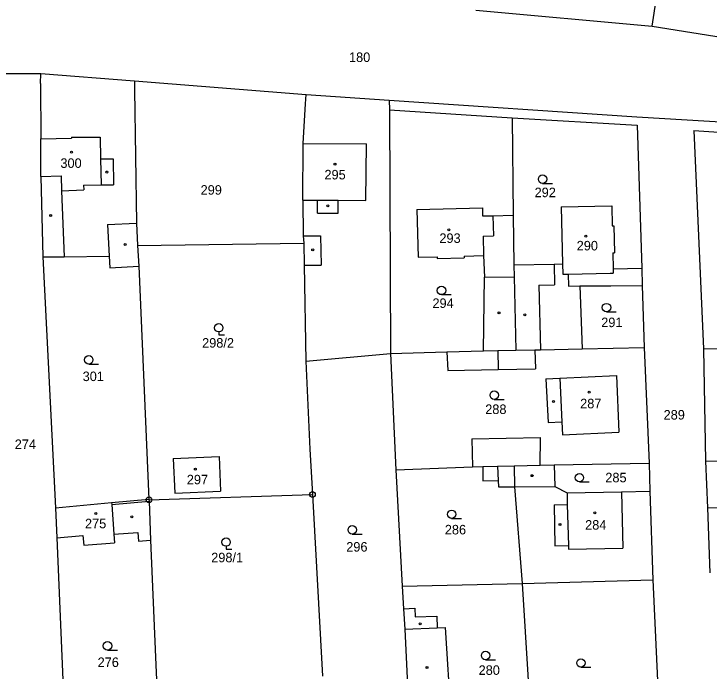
# Model space of a CAD drawing. Extents: x -779596 to -776743, y -1030330 to -1024513.
# Drawn here: x -778309.6 to -778185.6, y -1024804.1 to -1024686.7 of the extents above; entities that cross this region are included whole.
import ezdxf

# ---------------------------------------------------------------- set-up
doc = ezdxf.new("R2010")
doc.units = 0
for name, color, linetype in [('hranice parcel', 7, 'Continuous'), ('hranice vnitřní', 7, 'Continuous'), ('kultura', 7, 'Continuous'), ('Kód', 7, 'Continuous'), ('č_ parcel šipka', 7, 'Continuous'), ('č_pacel stav_', 7, 'Continuous'), ('č_parcel poz_', 7, 'Continuous')]:
    doc.layers.add(name, color=color, linetype=linetype)

msp = doc.modelspace()

# ---------------------------------------------------------------- linework, layer by layer
at = {"layer": 'hranice parcel'}
for points in [[(-778195.72, -1024688.95), (-778193.66, -1024675.24)], [(-778227.18, -1024686.07), (-778195.72, -1024688.95)], [(-778195.72, -1024688.95), (-778150.63, -1024696.12)], [(-778314.4, -1024697.39), (-778304.84, -1024697.38)], [(-778304.89, -1024699.14), (-778304.84, -1024697.38)], [(-778304.84, -1024697.38), (-778288.11, -1024698.71)], [(-778288.11, -1024698.71), (-778288.09, -1024700.32)], [(-778288.11, -1024698.71), (-778257.48, -1024701.14)], [(-778304.89, -1024699.14), (-778304.8, -1024709.04)], [(-778288.09, -1024700.32), (-778287.75, -1024724.09)], [(-778257.56, -1024702.77), (-778257.48, -1024701.14)], [(-778257.48, -1024701.14), (-778242.63, -1024702.14)], [(-778242.63, -1024702.14), (-778198.44, -1024705.1)], [(-778242.63, -1024702.14), (-778242.62, -1024703.86)], [(-778257.98, -1024709.85), (-778257.56, -1024702.77)], [(-778242.62, -1024703.86), (-778242.43, -1024747.35)], [(-778242.62, -1024703.86), (-778220.71, -1024705.3)], [(-778220.71, -1024705.3), (-778198.39, -1024706.6)], [(-778220.71, -1024705.3), (-778220.5, -1024722.69)], [(-778198.44, -1024705.1), (-778160.55, -1024707.39)], [(-778198.39, -1024706.6), (-778197.59, -1024732.16)], [(-778188.31, -1024707.53), (-778160.55, -1024709.39)], [(-778188.31, -1024707.53), (-778186.58, -1024746.54)], [(-778304.84, -1024715.78), (-778304.8, -1024709.04)], [(-778258.06, -1024719.99), (-778257.98, -1024709.85)], [(-778304.84, -1024715.78), (-778304.46, -1024730.09)], [(-778258.06, -1024719.99), (-778257.97, -1024726.37)], [(-778211.94, -1024721.17), (-778202.94, -1024720.98)], [(-778202.94, -1024720.98), (-778202.86, -1024724.6)], [(-778237.7, -1024721.67), (-778226.01, -1024721.39)], [(-778237.7, -1024721.67), (-778237.5, -1024730.18)], [(-778226.01, -1024721.39), (-778225.98, -1024722.82)], [(-778211.94, -1024721.17), (-778211.72, -1024731.38)], [(-778225.98, -1024722.82), (-778224.13, -1024722.78)], [(-778224.13, -1024722.78), (-778220.5, -1024722.69)], [(-778220.5, -1024722.69), (-778220.39, -1024731.53)], [(-778287.75, -1024724.09), (-778287.54, -1024728.1)], [(-778202.86, -1024724.6), (-778202.56, -1024724.6)], [(-778202.56, -1024724.6), (-778202.46, -1024729.39)], [(-778257.97, -1024726.37), (-778257.91, -1024727.68)], [(-778287.54, -1024728.1), (-778257.91, -1024727.68)], [(-778287.54, -1024728.1), (-778287.35, -1024731.8)], [(-778257.91, -1024727.68), (-778257.83, -1024731.63)], [(-778202.76, -1024729.4), (-778202.46, -1024729.39)], [(-778202.76, -1024729.4), (-778202.7, -1024732.24)], [(-778304.46, -1024730.09), (-778300.64, -1024730.12)], [(-778304.46, -1024730.09), (-778302.17, -1024774.92)], [(-778300.64, -1024730.12), (-778292.6, -1024729.98)], [(-778292.6, -1024729.98), (-778292.49, -1024732.07)], [(-778237.5, -1024730.18), (-778234.07, -1024730.1)], [(-778234.07, -1024730.1), (-778234.06, -1024730.4)], [(-778234.06, -1024730.4), (-778229.29, -1024730.29)], [(-778229.29, -1024729.99), (-778225.81, -1024729.9)], [(-778229.29, -1024729.99), (-778229.29, -1024730.29)], [(-778225.81, -1024729.9), (-778225.66, -1024733.77)], [(-778292.49, -1024732.07), (-778287.35, -1024731.8)], [(-778287.35, -1024731.8), (-778285.52, -1024773.4)], [(-778257.83, -1024731.63), (-778257.51, -1024748.73)], [(-778220.39, -1024731.53), (-778213.2, -1024731.4)], [(-778220.39, -1024731.53), (-778220.36, -1024733.69)], [(-778213.2, -1024731.4), (-778211.72, -1024731.38)], [(-778202.7, -1024732.24), (-778197.59, -1024732.16)], [(-778197.59, -1024732.16), (-778197.5, -1024735.24)], [(-778225.81, -1024746.92), (-778225.66, -1024733.77)], [(-778220.36, -1024733.69), (-778220.07, -1024746.77)], [(-778208.62, -1024735.32), (-778203.12, -1024735.28)], [(-778208.62, -1024735.32), (-778208.2, -1024746.57)], [(-778203.12, -1024735.28), (-778197.5, -1024735.24)], [(-778197.5, -1024735.24), (-778197.15, -1024746.33)], [(-778242.43, -1024747.35), (-778232.36, -1024747.09)], [(-778232.36, -1024747.09), (-778225.81, -1024746.92)], [(-778225.81, -1024746.92), (-778223.29, -1024746.85)], [(-778223.29, -1024746.85), (-778220.07, -1024746.77)], [(-778220.07, -1024746.77), (-778216.64, -1024746.75)], [(-778216.64, -1024746.75), (-778215.67, -1024746.73)], [(-778215.67, -1024746.73), (-778208.2, -1024746.57)], [(-778208.2, -1024746.57), (-778197.15, -1024746.33)], [(-778197.15, -1024746.33), (-778196.28, -1024766.95)], [(-778186.58, -1024746.54), (-778174.27, -1024746.3)], [(-778186.58, -1024746.54), (-778186.2, -1024766.58)], [(-778257.51, -1024748.73), (-778242.43, -1024747.35)], [(-778242.43, -1024747.35), (-778241.49, -1024768.13)], [(-778257.51, -1024748.73), (-778256.78, -1024764.46)], [(-778214.69, -1024751.9), (-778212.2, -1024751.79)], [(-778214.69, -1024751.9), (-778214.28, -1024759.68)], [(-778212.2, -1024751.79), (-778202.11, -1024751.32)], [(-778202.11, -1024751.32), (-778201.65, -1024761.42)], [(-778214.28, -1024759.68), (-778211.85, -1024759.57)], [(-778211.85, -1024759.57), (-778211.74, -1024761.89)], [(-778211.74, -1024761.89), (-778201.65, -1024761.42)], [(-778256.78, -1024764.46), (-778256.34, -1024772.55)], [(-778281.2, -1024766.11), (-778273.01, -1024765.75)], [(-778273.01, -1024765.75), (-778272.73, -1024771.94)], [(-778281.2, -1024766.11), (-778280.92, -1024772.31)], [(-778213.21, -1024767.28), (-778196.28, -1024766.95)], [(-778196.28, -1024766.95), (-778196.11, -1024771.96)], [(-778186.2, -1024766.58), (-778165.58, -1024766.14)], [(-778186.2, -1024766.58), (-778185.87, -1024774.95)], [(-778241.49, -1024768.13), (-778227.8, -1024767.63)], [(-778241.49, -1024768.13), (-778240.31, -1024788.94)], [(-778227.8, -1024767.63), (-778225.93, -1024767.58)], [(-778225.93, -1024767.58), (-778223.31, -1024767.52)], [(-778223.31, -1024767.52), (-778220.36, -1024767.45)], [(-778220.36, -1024767.45), (-778215.7, -1024767.33)], [(-778220.36, -1024767.45), (-778220.27, -1024771.18)], [(-778215.7, -1024767.33), (-778213.21, -1024767.28)], [(-778213.21, -1024767.28), (-778213.1, -1024771.11)], [(-778280.92, -1024772.31), (-778272.73, -1024771.94)], [(-778220.27, -1024771.18), (-778218.94, -1024788.46)], [(-778213.1, -1024771.11), (-778210.9, -1024772.27)], [(-778201.19, -1024772.07), (-778196.11, -1024771.96)], [(-778196.11, -1024771.96), (-778195.58, -1024787.78)], [(-778285.52, -1024773.5), (-778256.34, -1024772.55)], [(-778256.34, -1024772.55), (-778254.57, -1024805)], [(-778210.9, -1024772.27), (-778201.19, -1024772.07)], [(-778302.17, -1024774.92), (-778292.18, -1024774.01)], [(-778292.18, -1024774.01), (-778285.52, -1024773.4)], [(-778285.52, -1024773.5), (-778285.52, -1024773.4)], [(-778285.52, -1024773.5), (-778285.51, -1024773.75)], [(-778285.51, -1024773.75), (-778285.22, -1024780.72)], [(-778302.17, -1024774.92), (-778301.94, -1024780.27)], [(-778185.87, -1024774.95), (-778180.98, -1024774.86)], [(-778185.87, -1024774.95), (-778185.42, -1024786.53)], [(-778291.77, -1024779.64), (-778287.48, -1024779.32)], [(-778287.48, -1024779.32), (-778287.37, -1024780.91)], [(-778301.94, -1024780.27), (-778297.33, -1024779.85)], [(-778301.94, -1024780.27), (-778299.71, -1024833.83)], [(-778297.33, -1024779.85), (-778297.15, -1024781.58)], [(-778291.77, -1024779.64), (-778291.66, -1024781.17)], [(-778297.15, -1024781.58), (-778291.66, -1024781.17)], [(-778287.37, -1024780.91), (-778285.22, -1024780.72)], [(-778285.22, -1024780.72), (-778284.34, -1024801.62)], [(-778218.94, -1024788.46), (-778195.58, -1024787.78)], [(-778195.58, -1024787.78), (-778193.9, -1024825.06)], [(-778240.31, -1024788.94), (-778218.94, -1024788.46)], [(-778240.31, -1024788.94), (-778240.07, -1024792.96)], [(-778218.94, -1024788.46), (-778216.34, -1024829.72)], [(-778240.07, -1024792.96), (-778238.08, -1024792.87)], [(-778240.07, -1024792.96), (-778239.85, -1024796.61)], [(-778238.08, -1024792.87), (-778238.01, -1024794.41)], [(-778238.01, -1024794.41), (-778234.16, -1024794.25)], [(-778234.16, -1024794.25), (-778234.07, -1024796.37)], [(-778239.85, -1024796.61), (-778239.11, -1024812.84)], [(-778234.07, -1024796.37), (-778232.64, -1024796.31)], [(-778232.64, -1024796.31), (-778231.66, -1024812.23)], [(-778284.34, -1024801.62), (-778282.93, -1024834.15)]]:
    msp.add_lwpolyline(points, dxfattribs=at)
at = {"layer": 'hranice vnitřní'}
for points in [[(-778299.33, -1024708.75), (-778299.33, -1024708.95)], [(-778299.33, -1024708.75), (-778294.22, -1024708.75)], [(-778294.22, -1024708.75), (-778294.15, -1024712.61)], [(-778304.8, -1024709.04), (-778299.33, -1024708.95)], [(-778257.98, -1024709.85), (-778246.71, -1024709.94)], [(-778246.8, -1024720.03), (-778246.71, -1024709.94)], [(-778294.15, -1024712.61), (-778291.92, -1024712.6)], [(-778294.15, -1024712.61), (-778294.06, -1024717.28)], [(-778291.92, -1024712.6), (-778291.83, -1024717.24)], [(-778304.84, -1024715.78), (-778301.18, -1024715.68)], [(-778301.18, -1024715.68), (-778301.14, -1024718.31)], [(-778297.17, -1024717.34), (-778294.06, -1024717.28)], [(-778297.17, -1024717.34), (-778297.16, -1024718.17)], [(-778294.06, -1024717.28), (-778291.83, -1024717.24)], [(-778301.14, -1024718.31), (-778297.16, -1024718.17)], [(-778301.14, -1024718.31), (-778300.64, -1024730.12)], [(-778258.06, -1024719.99), (-778255.42, -1024720.01)], [(-778255.44, -1024722.31), (-778255.42, -1024720.01)], [(-778255.42, -1024720.01), (-778251.73, -1024719.99)], [(-778251.75, -1024722.34), (-778251.73, -1024719.99)], [(-778251.73, -1024719.99), (-778246.8, -1024720.03)], [(-778255.44, -1024722.31), (-778251.75, -1024722.34)], [(-778224.13, -1024722.78), (-778224.04, -1024726.39)], [(-778292.89, -1024724.36), (-778287.75, -1024724.09)], [(-778292.89, -1024724.36), (-778292.6, -1024729.98)], [(-778257.97, -1024726.37), (-778254.88, -1024726.34)], [(-778254.88, -1024726.34), (-778254.8, -1024731.58)], [(-778225.89, -1024726.43), (-778224.04, -1024726.39)], [(-778225.89, -1024726.43), (-778225.81, -1024729.9)], [(-778257.83, -1024731.63), (-778254.8, -1024731.58)], [(-778213.2, -1024731.4), (-778213.12, -1024735.13)], [(-778211.72, -1024731.38), (-778211.68, -1024733.23)], [(-778202.7, -1024732.24), (-778202.68, -1024733.04)], [(-778211.68, -1024733.23), (-778210.69, -1024733.21)], [(-778210.69, -1024733.21), (-778203.19, -1024733.05)], [(-778210.69, -1024733.21), (-778210.64, -1024735.34)], [(-778203.19, -1024733.05), (-778202.68, -1024733.04)], [(-778225.66, -1024733.77), (-778220.36, -1024733.69)], [(-778215.93, -1024735.19), (-778213.12, -1024735.13)], [(-778215.93, -1024735.19), (-778215.67, -1024746.73)], [(-778210.64, -1024735.34), (-778208.62, -1024735.32)], [(-778232.36, -1024747.09), (-778232.18, -1024750.44)], [(-778223.29, -1024746.85), (-778223.2, -1024750.25)], [(-778216.64, -1024746.75), (-778216.56, -1024750.11)], [(-778232.18, -1024750.44), (-778223.2, -1024750.25)], [(-778223.2, -1024750.25), (-778216.56, -1024750.11)], [(-778212.2, -1024751.79), (-778211.85, -1024759.57)], [(-778227.91, -1024762.6), (-778215.62, -1024762.39)], [(-778227.91, -1024762.6), (-778227.8, -1024767.63)], [(-778215.7, -1024767.33), (-778215.62, -1024762.39)], [(-778225.93, -1024767.58), (-778225.91, -1024770.1)], [(-778223.31, -1024767.52), (-778223.18, -1024770.03)], [(-778225.91, -1024770.1), (-778223.18, -1024770.03)], [(-778223.18, -1024770.03), (-778223.17, -1024771.2)], [(-778223.17, -1024771.2), (-778220.27, -1024771.18)], [(-778220.27, -1024771.18), (-778213.1, -1024771.11)], [(-778210.9, -1024772.27), (-778210.86, -1024774.35)], [(-778201.19, -1024772.07), (-778200.98, -1024782.14)], [(-778292.18, -1024774.01), (-778292.16, -1024774.34)], [(-778292.16, -1024774.34), (-778285.51, -1024773.75)], [(-778292.16, -1024774.34), (-778291.77, -1024779.64)], [(-778213.22, -1024774.4), (-778210.86, -1024774.35)], [(-778213.22, -1024774.4), (-778213.07, -1024781.73)], [(-778210.86, -1024774.35), (-778210.68, -1024781.68)], [(-778213.07, -1024781.73), (-778210.68, -1024781.68)], [(-778210.68, -1024781.68), (-778210.67, -1024782.34)], [(-778210.67, -1024782.34), (-778200.98, -1024782.14)], [(-778239.85, -1024796.61), (-778234.07, -1024796.37)]]:
    msp.add_lwpolyline(points, dxfattribs=at)
at = {"layer": 'kultura'}
for points in [[(-778215.28, -1024717), (-778213.53, -1024717)], [(-778233.32, -1024736.87), (-778231.57, -1024736.87)], [(-778203.87, -1024739.92), (-778202.12, -1024739.92)], [(-778273.07, -1024743.53), (-778273.07, -1024744.03), (-778272.047, -1024744.03)], [(-778296.27, -1024749.26), (-778294.52, -1024749.26)], [(-778223.9, -1024755.57), (-778222.15, -1024755.57)], [(-778208.71, -1024770.3), (-778206.96, -1024770.3)], [(-778231.5, -1024776.84), (-778229.75, -1024776.84)], [(-778249.24, -1024779.61), (-778247.49, -1024779.61)], [(-778271.76, -1024781.8), (-778271.76, -1024782.3), (-778270.737, -1024782.3)], [(-778292.91, -1024800.33), (-778291.16, -1024800.33)], [(-778225.44, -1024802.05), (-778223.69, -1024802.05)], [(-778208.43, -1024803.39), (-778206.68, -1024803.39)]]:
    msp.add_lwpolyline(points, dxfattribs=at)
for centre, radius in [((-778299.35, -1024711.44), 0.175), ((-778252.32, -1024713.59), 0.175), ((-778293.03, -1024714.97), 0.175), ((-778215.28, -1024716.25), 0.75), ((-778253.59, -1024721.01), 0.175), ((-778303.06, -1024722.74), 0.175), ((-778231.99, -1024725.27), 0.175), ((-778207.58, -1024726.41), 0.175), ((-778289.77, -1024727.9), 0.175), ((-778256.3, -1024728.87), 0.175), ((-778233.32, -1024736.12), 0.75), ((-778203.87, -1024739.17), 0.75), ((-778223.05, -1024740.1), 0.175), ((-778218.42, -1024740.49), 0.175), ((-778273.07, -1024742.78), 0.75), ((-778296.27, -1024748.51), 0.75), ((-778223.9, -1024754.82), 0.75), ((-778206.96, -1024754.3), 0.175), ((-778213.33, -1024755.93), 0.175), ((-778277.24, -1024768.05), 0.175), ((-778217.16, -1024769.19), 0.175), ((-778208.71, -1024769.55), 0.75), ((-778231.5, -1024776.09), 0.75), ((-778205.94, -1024775.84), 0.175), ((-778295.02, -1024775.97), 0.175), ((-778288.55, -1024776.54), 0.175), ((-778249.24, -1024778.86), 0.75), ((-778212.17, -1024777.92), 0.175), ((-778271.76, -1024781.05), 0.75), ((-778237.12, -1024795.63), 0.175), ((-778292.91, -1024799.58), 0.75), ((-778225.44, -1024801.3), 0.75), ((-778208.43, -1024802.64), 0.75), ((-778235.9, -1024803.44), 0.175)]:
    msp.add_circle(centre, radius, dxfattribs=at)
at = {"layer": 'Kód'}
for centre, radius in [((-778285.52, -1024773.5), 0.5), ((-778256.34, -1024772.55), 0.5), ((-778256.34, -1024772.55), 0.032), ((-778285.52, -1024773.5), 0.032)]:
    msp.add_circle(centre, radius, dxfattribs=at)

# ---------------------------------------------------------------- texts
at = {"layer": 'č_ parcel šipka'}
msp.add_text('180', height=1.7, dxfattribs=at).set_placement((-778249.82, -1024695.32))
at = {"layer": 'č_pacel stav_'}
for s, p in [('300', (-778301.32, -1024714.23)), ('295', (-778254.2, -1024716.29)), ('293', (-778233.69, -1024727.63)), ('290', (-778209.19, -1024728.97)), ('287', (-778208.57, -1024757.16)), ('297', (-778278.76, -1024770.74)), ('275', (-778296.93, -1024778.59)), ('284', (-778207.68, -1024778.83))]:
    msp.add_text(s, height=1.7, dxfattribs=at).set_placement(p)
at = {"layer": 'č_parcel poz_'}
for s, p in [('299', (-778276.3, -1024719.02)), ('292', (-778216.7, -1024719.46)), ('294', (-778234.93, -1024739.24)), ('291', (-778204.81, -1024742.67)), ('298/2', (-778276.03, -1024746.33)), ('301', (-778297.35, -1024752.3)), ('288', (-778225.51, -1024758.18)), ('289', (-778193.68, -1024759.17)), ('274', (-778309.47, -1024764.43)), ('285', (-778204.08, -1024770.38)), ('286', (-778232.72, -1024779.68)), ('296', (-778250.31, -1024782.75)), ('298/1', (-778274.41, -1024784.66)), ('276', (-778294.68, -1024803.36)), ('280', (-778226.69, -1024804.76))]:
    msp.add_text(s, height=1.7, dxfattribs=at).set_placement(p)

doc.saveas('drawing.dxf')
